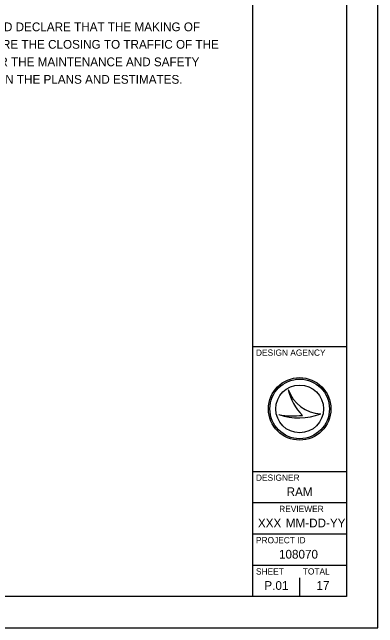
# Model space of a CAD drawing. Extents: x 0 to 34, y 0 to 22.
# Drawn here: x 28.15 to 34, y 0 to 9.84 of the extents above; entities that cross this region are included whole.
import ezdxf

# ---------------------------------------------------------------- set-up
doc = ezdxf.new("R2010")
doc.units = 0
for name, color, linetype in [('SH_Border', 7, 'Continuous'), ('SH_Cut_Line', 7, 'Continuous'), ('SH_Data', 7, 'Continuous'), ('SH_Text', 7, 'Continuous')]:
    doc.layers.add(name, color=color, linetype=linetype)

msp = doc.modelspace()

# ---------------------------------------------------------------- linework, layer by layer
at = {"layer": 'SH_Border'}
for p, q in [((32, 0.5), (32, 21.5)), ((32, 4.5), (33.5, 4.5)), ((32, 2.5), (33.5, 2.5)), ((32, 2), (33.5, 2)), ((32, 1.5), (33.5, 1.5)), ((32, 1), (33.5, 1))]:
    msp.add_line(p, q, dxfattribs=at)
msp.add_lwpolyline([(1.5, 21.5), (33.5, 21.5), (33.5, 0.5), (1.5, 0.5)], close=True, dxfattribs=at)
at = {"layer": 'SH_Cut_Line'}
msp.add_lwpolyline([(0, 0), (34, 0), (34, 22), (0, 22)], close=True, dxfattribs=at)
at = {"layer": 'SH_Data'}
for p, q in [((32.5674, 3.8096), (32.5675, 3.8096)), ((32.75, 3.5), (32.75, 3.5)), ((32.4172, 3.4095), (32.4172, 3.4095)), ((33.0873, 3.4185), (33.0873, 3.4185)), ((32.75, 0.5), (32.75, 0.8)), ((32.375, 0.675), (32.375, 0.675))]:
    msp.add_line(p, q, dxfattribs=at)
for radius in [0.5, 0.4768, 0.4768, 0.3822]:
    msp.add_circle((32.75, 3.5), radius, dxfattribs=at)
for centre, radius, start, end in [((33.1159, 3.9976), 0.5798, 198.92567, 198.93195), ((33.3467, 3.9701), 0.7956, 191.63793, 191.64215), ((33.1159, 3.9976), 0.5798, 198.93195, 267.16574), ((33.3467, 3.9701), 0.7956, 191.64215, 226.09467), ((32.7394, 4.37), 1.0131, 251.45764, 290.08324), ((32.648, 4.6543), 1.2661, 259.49639, 259.49952), ((32.7394, 4.37), 1.0131, 251.45274, 251.45764), ((32.648, 4.6543), 1.2661, 259.49952, 276.66723)]:
    msp.add_arc(centre, radius, start, end, dxfattribs=at)

# ---------------------------------------------------------------- texts
for s, height, p in [('DESIGN AGENCY', 0.1, (32.05, 4.35)), ('DESIGNER', 0.1, (32.05, 2.35)), ('RAM', 0.14, (32.5412, 2.105)), ('REVIEWER', 0.1, (32.4218, 1.85)), ('XXX', 0.14, (32.0809, 1.605)), ('MM-DD-YY', 0.14, (32.5273, 1.605)), ('PROJECT ID', 0.1, (32.05, 1.35)), ('108070', 0.14, (32.4186, 1.105)), ('SHEET', 0.1, (32.05, 0.85)), ('TOTAL', 0.1, (32.8, 0.85)), ('P.01', 0.14, (32.1844, 0.605)), ('17', 0.14, (33.0183, 0.605))]:
    msp.add_text(s, height=height, dxfattribs=at).set_placement(p)
at = {"layer": 'SH_Text'}
for s, p in [('I HEREBY APPROVE THESE PLANS AND DECLARE THAT THE MAKING OF', (24.5279, 9.5414)), ('THIS IMPROVEMENT WILL NOT REQUIRE THE CLOSING TO TRAFFIC OF THE', (24.5279, 9.2614)), ('HIGHWAY AND THAT PROVISIONS FOR THE MAINTENANCE AND SAFETY', (24.5279, 8.9814)), ('OF TRAFFIC WILL BE AS SET FORTH ON THE PLANS AND ESTIMATES.', (24.5279, 8.7014))]:
    msp.add_text(s, height=0.14, dxfattribs=at).set_placement(p)

doc.saveas('drawing.dxf')
